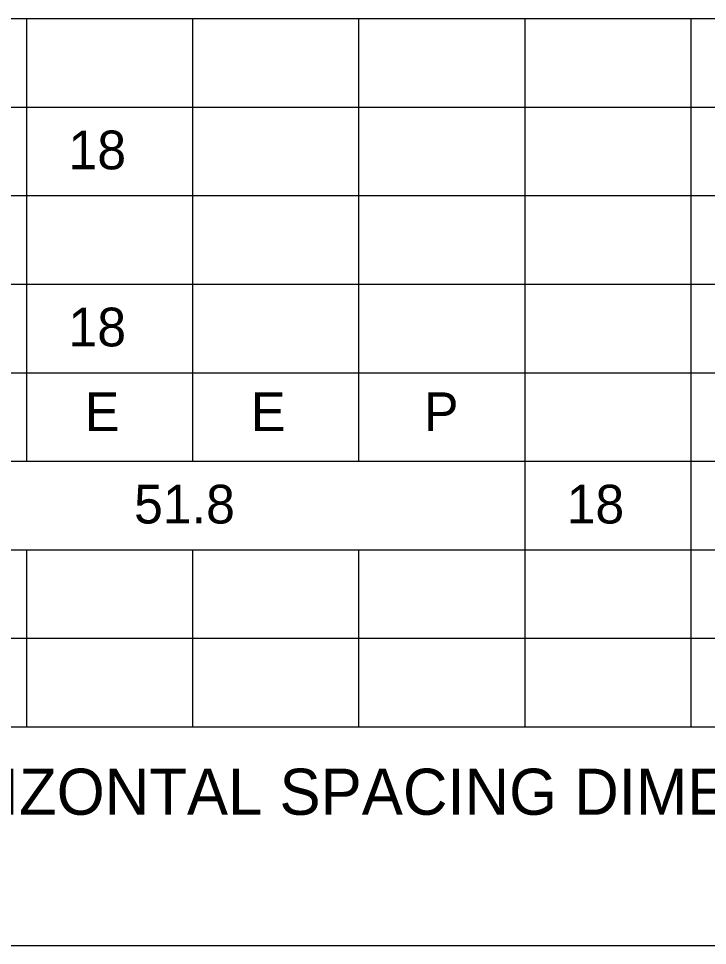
# Model space of a CAD drawing. Extents: x 10268312 to 10268706, y 2142548 to 2142786.
# Drawn here: x 10268330.83 to 10268343.28, y 2142640.28 to 2142657.03 of the extents above; entities that cross this region are included whole.
import ezdxf

# ---------------------------------------------------------------- set-up
doc = ezdxf.new("R2010")
doc.units = 0
for name, color, linetype in [('SheetBorder_dp', 7, 'Continuous'), ('SumBoxLines_dp', 7, 'Continuous'), ('SumBoxLinesMin_dp', 7, 'Continuous'), ('TextLabel', 7, 'Continuous'), ('TextNotes', 7, 'Continuous')]:
    doc.layers.add(name, color=color, linetype=linetype)

msp = doc.modelspace()

# ---------------------------------------------------------------- linework, layer by layer
at = {"layer": 'SheetBorder_dp'}
msp.add_line((10268317.73, 2142640.282), (10268471.73, 2142640.282), dxfattribs=at)
at = {"layer": 'SumBoxLines_dp'}
for p, q in [((10268318.48, 2142657.032), (10268393.98, 2142657.032)), ((10268330.98, 2142657.032), (10268330.98, 2142653.832)), ((10268333.98, 2142657.032), (10268333.98, 2142653.832)), ((10268336.98, 2142657.032), (10268336.98, 2142653.832)), ((10268339.98, 2142657.032), (10268339.98, 2142653.832)), ((10268342.98, 2142657.032), (10268342.98, 2142655.432)), ((10268342.98, 2142655.432), (10268342.98, 2142650.632)), ((10268318.48, 2142653.832), (10268393.98, 2142653.832)), ((10268330.98, 2142653.832), (10268330.98, 2142649.032)), ((10268333.98, 2142653.832), (10268333.98, 2142649.032)), ((10268336.98, 2142653.832), (10268336.98, 2142649.032)), ((10268339.98, 2142653.832), (10268339.98, 2142650.632)), ((10268318.48, 2142650.632), (10268393.98, 2142650.632)), ((10268339.98, 2142650.632), (10268339.98, 2142647.432)), ((10268342.98, 2142650.632), (10268342.98, 2142647.432)), ((10268318.48, 2142647.432), (10268393.98, 2142647.432)), ((10268330.98, 2142647.432), (10268330.98, 2142644.232)), ((10268333.98, 2142647.432), (10268333.98, 2142644.232)), ((10268336.98, 2142647.432), (10268336.98, 2142644.232)), ((10268339.98, 2142647.432), (10268339.98, 2142644.232)), ((10268342.98, 2142647.432), (10268342.98, 2142644.232)), ((10268318.48, 2142644.232), (10268393.98, 2142644.232))]:
    msp.add_line(p, q, dxfattribs=at)
at = {"layer": 'SumBoxLinesMin_dp'}
for p, q in [((10268318.48, 2142655.432), (10268393.98, 2142655.432)), ((10268318.48, 2142652.232), (10268393.98, 2142652.232)), ((10268318.48, 2142649.032), (10268393.98, 2142649.032)), ((10268318.48, 2142645.832), (10268393.98, 2142645.832))]:
    msp.add_line(p, q, dxfattribs=at)

# ---------------------------------------------------------------- texts
at = {"layer": 'TextLabel'}
for s, p in [('18', (10268331.737, 2142654.307)), ('18', (10268331.737, 2142651.107)), ('E', (10268332.033, 2142649.576)), ('E', (10268335.033, 2142649.576)), ('P', (10268338.16, 2142649.576)), ('51.8', (10268332.922, 2142647.907)), ('18', (10268340.737, 2142647.907))]:
    msp.add_text(s, height=0.7, dxfattribs=at).set_placement(p)
at = {"layer": 'TextNotes'}
msp.add_text('NOTE:  WIDTH - HORIZONTAL SPACING DIMENSIONS ARE IN INCHES.', height=0.83333, dxfattribs=at).set_placement((10268319.392, 2142642.643))

doc.saveas('drawing.dxf')
